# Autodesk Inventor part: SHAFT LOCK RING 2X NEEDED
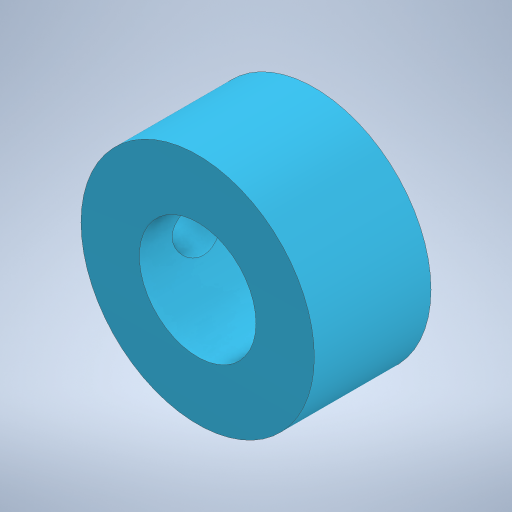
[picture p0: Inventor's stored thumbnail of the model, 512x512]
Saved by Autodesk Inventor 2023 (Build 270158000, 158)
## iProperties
Created: 2025-07
Part Number: SHAFT LOCK RING 2X NEEDED
Material: Generic
Document SubType Name: Modeling
Designer: erjon
Density: 1 g/cm^3
Appearance: Default
Author: erjon
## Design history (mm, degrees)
feature "Base1"
sketch "Sketch2"
  geometry: L1 (8, 8)-(-8, 8) reference; L2 (0, 8)-(0, 0); C1 r 1.75 at (0, 4)
  constraints: 2 end point, 2 midpoint, 1 centre point, 1 vertical
  dimensions: "d0" = 3.5 diameter of C1
extrude "Extrusion1" cut sketch "Sketch2" distance "d1" = 50; taper "d2" = 0 deg
body "Solid1"
